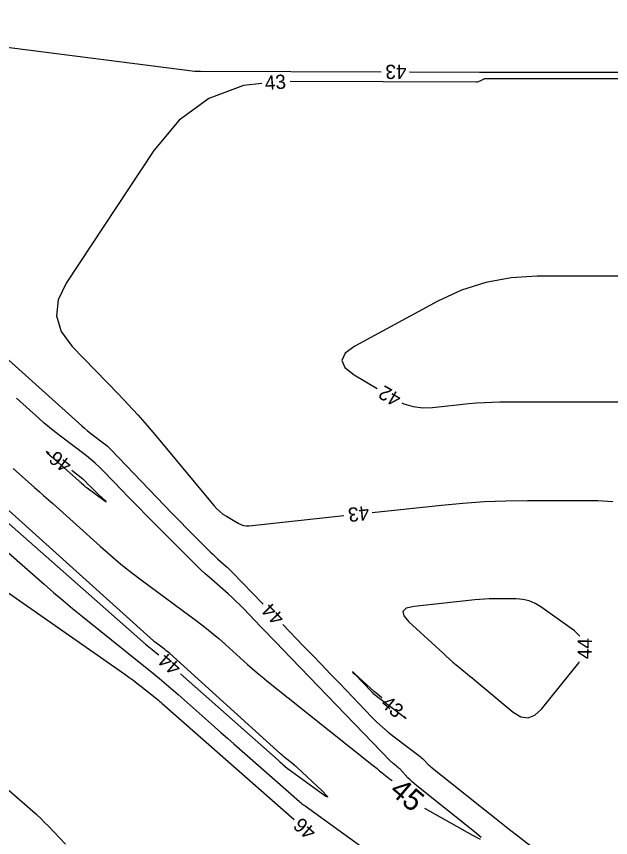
# Model space of a CAD drawing. Extents: x 2384780 to 2405861, y 547869 to 573706.
# Drawn here: x 2389694.1 to 2389777.8, y 552692.8 to 552808.4 of the extents above; entities that cross this region are included whole.
import ezdxf

# ---------------------------------------------------------------- set-up
doc = ezdxf.new("R2010")
doc.units = 0
doc.layers.add('Old_Level_60', color=7, linetype='Continuous')
doc.layers.add('Old_Level_61', color=7, linetype='Continuous')

msp = doc.modelspace()

# ---------------------------------------------------------------- linework, layer by layer
at = {"layer": 'Old_Level_60'}
for points in [[(2389646.548, 552812.44925), (2389651.91025, 552812.178), (2389653.06, 552812.092), (2389654.2015, 552811.95075), (2389655.335, 552811.7545), (2389656.46, 552811.503), (2389672.938, 552807.3995), (2389676.479, 552806.573), (2389680.0395, 552805.852), (2389683.61975, 552805.2365), (2389687.22, 552804.7265), (2389719.24975, 552800.66925), (2389719.32675, 552800.66075), (2389719.404, 552800.65475), (2389719.48125, 552800.651), (2389719.55875, 552800.6495), (2389719.812, 552800.649), (2389719.8665, 552800.649), (2389719.92075, 552800.64875), (2389719.975, 552800.64875), (2389720.02925, 552800.6485), (2389745.4685, 552800.56375)], [(2389749.4685, 552800.55025), (2389759.3255, 552800.5175), (2389759.40325, 552800.51725), (2389759.48125, 552800.517), (2389759.55925, 552800.517), (2389759.63725, 552800.51725), (2389759.89175, 552800.51775), (2389759.94625, 552800.51775), (2389760.001, 552800.51775), (2389760.0555, 552800.518), (2389760.11, 552800.518), (2389799.328, 552800.518)], [(2389728.681, 552798.9005), (2389726.0885, 552798.62225), (2389721.232, 552796.80775), (2389717.0305, 552793.7705), (2389713.48375, 552789.5105), (2389701.13325, 552770.82175), (2389700.00125, 552768.475), (2389699.7625, 552766.21175), (2389700.4165, 552764.032), (2389701.96375, 552761.93575), (2389708.47625, 552755.224), (2389709.8575, 552753.773), (2389711.21, 552752.296), (2389712.534, 552750.7935), (2389713.82925, 552749.26525), (2389721.91825, 552739.53225), (2389722.31225, 552739.09675), (2389722.739, 552738.699), (2389723.198, 552738.33925), (2389723.6895, 552738.0175), (2389725.348, 552737.0285), (2389725.7105, 552736.8485), (2389726.087, 552736.7325), (2389726.4775, 552736.68075), (2389726.88175, 552736.69275), (2389740.2335, 552738.12675)], [(2389799.9155, 552799.59725), (2389760.5235, 552799.59725), (2389760.46325, 552799.59725), (2389760.40275, 552799.59725), (2389760.34225, 552799.59725), (2389760.282, 552799.59725), (2389760.0845, 552799.59725), (2389760.043, 552799.59475), (2389760.0025, 552799.58725), (2389759.9635, 552799.5745), (2389759.9255, 552799.557), (2389759.36325, 552799.25275), (2389759.24075, 552799.19575), (2389759.114, 552799.155), (2389758.983, 552799.131), (2389758.84825, 552799.123), (2389732.66425, 552799.2105)], [(2389785.6985, 552771.8195), (2389767.45025, 552771.8195), (2389763.78125, 552771.59775), (2389760.2245, 552770.933), (2389756.78, 552769.825), (2389753.4475, 552768.2735), (2389741.756, 552761.94675), (2389740.4015, 552760.964), (2389739.936, 552759.963), (2389740.3595, 552758.94325), (2389741.6715, 552757.905), (2389744.8905, 552755.9855)], [(2389688.84075, 552763.76525), (2389703.31525, 552750.76), (2389703.71675, 552750.40675), (2389704.12525, 552750.06225), (2389704.541, 552749.7265), (2389704.964, 552749.39925), (2389706.357, 552748.34425), (2389706.6505, 552748.11275), (2389706.9345, 552747.87025), (2389707.2085, 552747.61675), (2389707.47275, 552747.35225), (2389715.99625, 552738.48075), (2389716.65225, 552737.80125), (2389717.31175, 552737.1245), (2389717.97425, 552736.451), (2389718.63975, 552735.78075), (2389721.105, 552733.31), (2389721.432, 552732.9875), (2389721.76375, 552732.6705), (2389722.101, 552732.35875), (2389722.443, 552732.0525), (2389723.56875, 552731.06075), (2389723.80775, 552730.846), (2389724.042, 552730.6265), (2389724.272, 552730.402), (2389724.4975, 552730.173), (2389728.863, 552725.6475)], [(2389748.36525, 552754.00875), (2389748.6635, 552753.86075), (2389749.96575, 552753.45975), (2389751.3165, 552753.28025), (2389752.71575, 552753.32225), (2389757.81475, 552753.87), (2389758.90825, 552753.9725), (2389760.00325, 552754.046), (2389761.09975, 552754.09), (2389762.19775, 552754.1045), (2389791.923, 552754.1045)], [(2389698.71375, 552746.8695), (2389698.56425, 552746.9795), (2389698.3205, 552747.125), (2389698.51125, 552746.91475), (2389699.137, 552746.349), (2389702.9135, 552743.0195), (2389702.9925, 552742.9495), (2389703.0715, 552742.8795), (2389703.15025, 552742.809), (2389703.22875, 552742.7385)], [(2389703.22875, 552742.7385), (2389703.595, 552742.40875), (2389703.70825, 552742.30925), (2389703.824, 552742.2125), (2389703.94175, 552742.1185), (2389704.062, 552742.0275), (2389706.436, 552740.27275), (2389706.6885, 552740.0935), (2389706.783, 552740.04625), (2389706.71925, 552740.1305), (2389706.4975, 552740.3465), (2389705.449, 552741.3295), (2389705.272, 552741.49675), (2389705.0965, 552741.6655), (2389704.9225, 552741.8355), (2389704.75, 552742.007), (2389704.061, 552742.6975), (2389704.0045, 552742.7545), (2389703.94825, 552742.81175), (2389703.89225, 552742.86925), (2389703.8365, 552742.92675), (2389703.655, 552743.11575), (2389703.61525, 552743.1555), (2389703.57425, 552743.1935), (2389703.5315, 552743.23), (2389703.4875, 552743.2645), (2389701.9075, 552744.46125)], [(2389744.2105, 552738.55375), (2389753.96, 552739.60075), (2389756.98225, 552739.8845), (2389760.00875, 552740.08725), (2389763.0395, 552740.20875), (2389766.07475, 552740.2495), (2389775.997, 552740.2495), (2389778.0735, 552740.09475)], [(2389717.20075, 552715.8505), (2389730.951, 552703.7015), (2389731.10725, 552703.56375), (2389731.2635, 552703.42575), (2389731.42, 552703.288), (2389731.57625, 552703.15025), (2389732.29225, 552702.52025), (2389732.2995, 552702.51425), (2389732.3065, 552702.50825), (2389732.314, 552702.5025), (2389732.3215, 552702.497), (2389732.346, 552702.479), (2389732.3515, 552702.47525), (2389732.35675, 552702.47125), (2389732.362, 552702.4675), (2389732.36725, 552702.46375), (2389737.03275, 552699.09775), (2389737.70175, 552698.63675), (2389737.9545, 552698.519), (2389737.79125, 552698.745), (2389737.2115, 552699.3145), (2389733.5985, 552702.71475), (2389733.567, 552702.74375), (2389733.53475, 552702.77225), (2389733.502, 552702.8), (2389733.46875, 552702.827), (2389733.359, 552702.9145), (2389733.3355, 552702.93325), (2389733.312, 552702.952), (2389733.2885, 552702.97075), (2389733.265, 552702.9895), (2389732.19525, 552703.8415), (2389731.9675, 552704.02575), (2389731.74275, 552704.2135), (2389731.52075, 552704.40475), (2389731.302, 552704.5995), (2389715.6565, 552718.7355), (2389715.44425, 552718.9225), (2389715.22775, 552719.10425), (2389715.00675, 552719.2805), (2389714.78125, 552719.4515), (2389714.03775, 552720.001), (2389713.87975, 552720.12075), (2389713.725, 552720.244), (2389713.57325, 552720.371), (2389713.4245, 552720.50175), (2389693.059, 552738.83725)], [(2389691.9405, 552738.0005), (2389712.30225, 552720.0445), (2389712.5345, 552719.842), (2389712.7695, 552719.64225), (2389713.0065, 552719.4455), (2389713.246, 552719.2515), (2389714.03225, 552718.622), (2389714.1955, 552718.48975)], [(2389691.1515, 552728.5315), (2389709.38875, 552715.80875), (2389709.96425, 552715.40025), (2389710.53275, 552714.9825), (2389711.09425, 552714.55525), (2389711.64875, 552714.11875), (2389714.11275, 552712.14625), (2389714.16625, 552712.10275), (2389714.2195, 552712.0585), (2389714.27225, 552712.01375), (2389714.32425, 552711.96825), (2389714.4935, 552711.81875), (2389714.52975, 552711.78675), (2389714.566, 552711.75475), (2389714.6025, 552711.72275), (2389714.63875, 552711.69075), (2389733.2035, 552695.35575)], [(2389773.438, 552721.1705), (2389772.67525, 552721.901), (2389767.95425, 552725.278), (2389767.152, 552725.7665), (2389766.30475, 552726.11525), (2389765.41275, 552726.3245), (2389764.476, 552726.39425), (2389761.34275, 552726.39425), (2389760.67175, 552726.38525), (2389760.002, 552726.35825), (2389759.333, 552726.3135), (2389758.665, 552726.25075), (2389750.09775, 552725.33075), (2389749.01175, 552725.0825), (2389748.53, 552724.6355), (2389748.65275, 552723.98975), (2389749.38, 552723.14575)], [(2389731.64, 552722.7685), (2389734.50575, 552719.7975), (2389735.78775, 552718.4685), (2389737.0695, 552717.13925), (2389738.351, 552715.81), (2389739.6325, 552714.48075), (2389744.1255, 552709.8195), (2389744.88275, 552709.0635), (2389745.66675, 552708.3375), (2389746.478, 552707.642), (2389747.316, 552706.97675), (2389750.957, 552704.19825), (2389751.121, 552704.0675), (2389751.27925, 552703.9305), (2389751.4315, 552703.78725), (2389751.57825, 552703.63725), (2389752.04775, 552703.1375), (2389752.15025, 552703.03225), (2389752.25625, 552702.931), (2389752.36575, 552702.8335), (2389752.47875, 552702.74), (2389760.04525, 552696.7085), (2389761.67025, 552695.42075), (2389763.3025, 552694.14225), (2389764.942, 552692.87325), (2389766.589, 552691.61325)], [(2389749.38, 552723.14575), (2389754.184, 552718.743), (2389754.644, 552718.32675), (2389755.10875, 552717.91625), (2389755.57875, 552717.5115), (2389756.05375, 552717.1125), (2389757.61325, 552715.81875), (2389757.9475, 552715.5415), (2389758.28175, 552715.26425), (2389758.616, 552714.987), (2389758.95025, 552714.70975), (2389764.0595, 552710.47125), (2389765.129, 552709.815), (2389766.148, 552709.663), (2389767.11625, 552710.01475), (2389768.034, 552710.8705), (2389773.291, 552717.39775), (2389773.39125, 552717.56675)], [(2389745.58825, 552712.444), (2389745.54525, 552712.4795), (2389745.01475, 552712.92525), (2389744.48975, 552713.37725), (2389743.9705, 552713.83575), (2389743.457, 552714.30075), (2389741.78825, 552715.83), (2389741.5175, 552716.073), (2389741.42025, 552716.147), (2389741.49675, 552716.0515), (2389741.7465, 552715.78725)], [(2389741.7465, 552715.78725), (2389744.04525, 552713.40425), (2389744.07225, 552713.37625), (2389744.099, 552713.34825), (2389744.126, 552713.32025), (2389744.153, 552713.29225), (2389744.24125, 552713.201), (2389744.2605, 552713.18175), (2389744.28025, 552713.16325), (2389744.301, 552713.1455), (2389744.32225, 552713.12875), (2389748.17675, 552710.187), (2389748.7995, 552709.71825), (2389749.016, 552709.573), (2389748.82575, 552709.75125), (2389748.66425, 552709.887)], [(2389701.048, 552691.87975), (2389698.62625, 552694.4125), (2389698.10125, 552694.94875), (2389697.564, 552695.472), (2389697.0145, 552695.98275), (2389696.45275, 552696.4805), (2389693.1195, 552699.365), (2389692.40475, 552699.9825), (2389691.68875, 552700.59875), (2389691.44625, 552700.80675)]]:
    msp.add_lwpolyline(points, dxfattribs=at)
at = {"layer": 'Old_Level_61'}
for points in [[(2389759.56875, 552692.80225), (2389758.61375, 552693.606), (2389750.4885, 552700.083), (2389750.16225, 552700.35275), (2389749.84625, 552700.63375), (2389749.54075, 552700.92575), (2389749.24525, 552701.22925), (2389748.13525, 552702.411), (2389748.01075, 552702.53825), (2389747.88125, 552702.66), (2389747.747, 552702.7765), (2389747.60775, 552702.88725), (2389747.14475, 552703.2405), (2389747.04725, 552703.318), (2389746.95275, 552703.399), (2389746.8615, 552703.4835), (2389746.77325, 552703.57175), (2389731.53725, 552719.37775), (2389730.78875, 552720.15425), (2389730.04, 552720.93075), (2389729.29125, 552721.707), (2389728.5425, 552722.4835), (2389726.09625, 552725.0195), (2389725.56675, 552725.55725), (2389725.02675, 552726.08425), (2389724.476, 552726.6), (2389723.91475, 552727.1045), (2389721.27, 552729.4345), (2389720.70725, 552729.93825), (2389720.153, 552730.45075), (2389719.60725, 552730.972), (2389719.0695, 552731.50225), (2389712.266, 552738.3215), (2389711.44825, 552739.145), (2389710.63425, 552739.9725), (2389709.82425, 552740.80375), (2389709.01825, 552741.63875), (2389706.39125, 552744.37275), (2389705.81775, 552744.94675), (2389705.223, 552745.49675), (2389704.60725, 552746.023), (2389703.97, 552746.5255), (2389700.329, 552749.28275), (2389699.55525, 552749.88125), (2389698.79475, 552750.496), (2389698.047, 552751.12625), (2389697.3125, 552751.7725), (2389694.13825, 552754.62475)], [(2389693.66675, 552744.73875), (2389696.66875, 552742.092), (2389697.31125, 552741.524), (2389697.95225, 552740.95425), (2389698.592, 552740.383), (2389699.23, 552739.81), (2389705.9075, 552733.79825), (2389707.353, 552732.528), (2389708.82775, 552731.29375), (2389710.33225, 552730.09525), (2389711.86575, 552728.933), (2389719.61025, 552723.209), (2389720.629, 552722.4365), (2389721.62775, 552721.63975), (2389722.60675, 552720.81875), (2389723.56575, 552719.97325), (2389726.66625, 552717.172), (2389727.33525, 552716.577), (2389728.013, 552715.9925), (2389728.7, 552715.41875), (2389729.39575, 552714.8555), (2389744.17875, 552703.0805), (2389744.53925, 552702.79325), (2389744.9, 552702.506), (2389745.2605, 552702.21875), (2389745.621, 552701.9315), (2389746.799, 552700.99325), (2389747.01425, 552700.818)], [(2389691.834, 552733.9045), (2389698.01075, 552728.4575), (2389699.341, 552727.29825), (2389700.685, 552726.15525), (2389702.04225, 552725.02825), (2389703.41325, 552723.91725), (2389711.601, 552717.3625), (2389712.94125, 552716.27625), (2389714.268, 552715.174), (2389715.581, 552714.05575), (2389716.88075, 552712.92125), (2389721.1045, 552709.1895), (2389722.00975, 552708.39), (2389722.9155, 552707.591), (2389723.82175, 552706.7925), (2389724.72825, 552705.9945), (2389733.95725, 552697.874), (2389734.03325, 552697.80875), (2389734.1105, 552697.74525), (2389734.1895, 552697.6835), (2389734.26975, 552697.6235), (2389734.53475, 552697.43075), (2389734.5915, 552697.3895), (2389734.64825, 552697.34825), (2389734.705, 552697.30725), (2389734.762, 552697.266), (2389744.61025, 552690.16075)], [(2389751.58225, 552696.95125), (2389758.316, 552693.164), (2389759.42, 552692.58125)]]:
    msp.add_lwpolyline(points, dxfattribs=at)

# ---------------------------------------------------------------- texts
at = {"layer": 'Old_Level_60'}
for s, rotation, p in [('43', 179.8087972, (2389749.0545, 552801.55175)), ('43', 4.4489694, (2389729.1695, 552797.9945)), ('42', 150.3655417, (2389748.46425, 552755.05575)), ('46', 142.9824111, (2389702.097, 552745.57575)), ('43', 186.1294556, (2389743.68875, 552739.5035)), ('44', 133.9676722, (2389731.99875, 552723.83675)), ('44', 89.2561083, (2389775.10325, 552717.89275)), ('44', 138.7106972, (2389717.47425, 552716.94925)), ('43', 320.2677056, (2389745.27125, 552711.4095)), ('46', 138.5422417, (2389736.4765, 552693.804))]:
    msp.add_text(s, height=2, rotation=rotation, dxfattribs=at).set_placement(p)
at = {"layer": 'Old_Level_61'}
msp.add_text('45', height=3, rotation=319.7521417, dxfattribs=at).set_placement((2389746.49425, 552699.12975))

doc.saveas('drawing.dxf')
